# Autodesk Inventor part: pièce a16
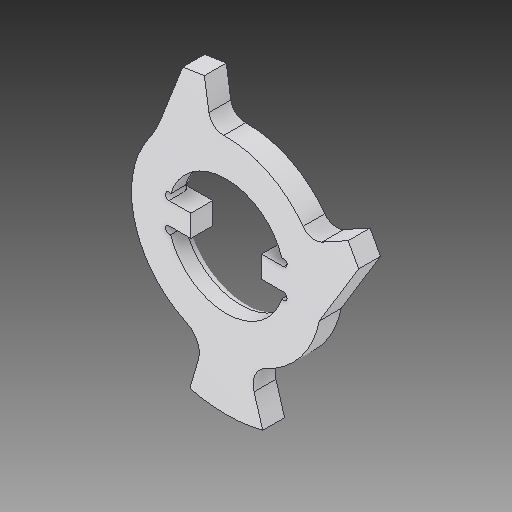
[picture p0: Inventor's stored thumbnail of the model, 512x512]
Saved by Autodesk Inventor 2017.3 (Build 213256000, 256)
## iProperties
Created: 2007-12
Part Number: pièce a16
Material: solidworks materials|Alliage 7079|22
Document SubType Name: Modeling
Designer: ficho
Density: 2.7 g/cm^3
Appearance: 227,227,233
Author: ficho
Sending System: SolidWorks 2009
Last Author: christophe
Last Saved: 2011-01-23
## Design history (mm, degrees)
feature "Congé7"
node "Solide1"
